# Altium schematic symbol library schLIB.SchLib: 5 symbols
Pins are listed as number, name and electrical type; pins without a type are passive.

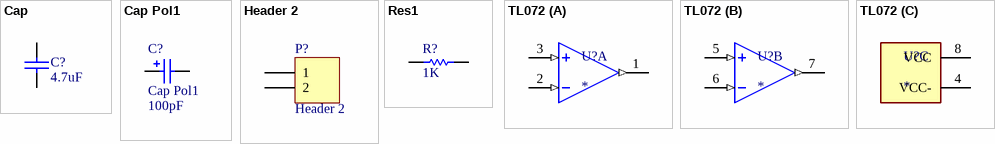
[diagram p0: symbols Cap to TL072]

## Cap
designator C?  value 4.7uF  (hidden comment: Cap)
Capacitor
footprint CAP200
pins: 1, 2

## Cap Pol1
designator C?  value 100pF
Polarized Capacitor (Radial)
footprint CAPPR2.5-6.3X11
pins: 1, 2
1 alternate drawing of the same symbol

## Header 2
designator P?
Header, 2-Pin
footprint HDR1X2 (Connector; Header; 2 Position)
footprint HDR1X2 (Connector; Header; 2 Position)
pins: 1, 2

## Res1
designator R?  value 1K  (hidden comment: Res1)
Resistor
footprint AXIAL-0.4 (Axial Device, Thru-Hole; 2 Leads; 0.4 in Pin Spacing)
pins: 1, 2

## TL072
designator U?
Dual standard operational amplifier 8-PDIP 0 to 70; MP: LM358P; MF: Texas Instruments
footprint DIP-8
part A pins: 1 OUT1 (out), 2 -IN1 (in), 3 +IN1 (in)
part B pins: 5 +IN2 (in), 6 -IN2 (in), 7 OUT2 (out)
part C pins: 4 VCC- (power), 8 VCC (power)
